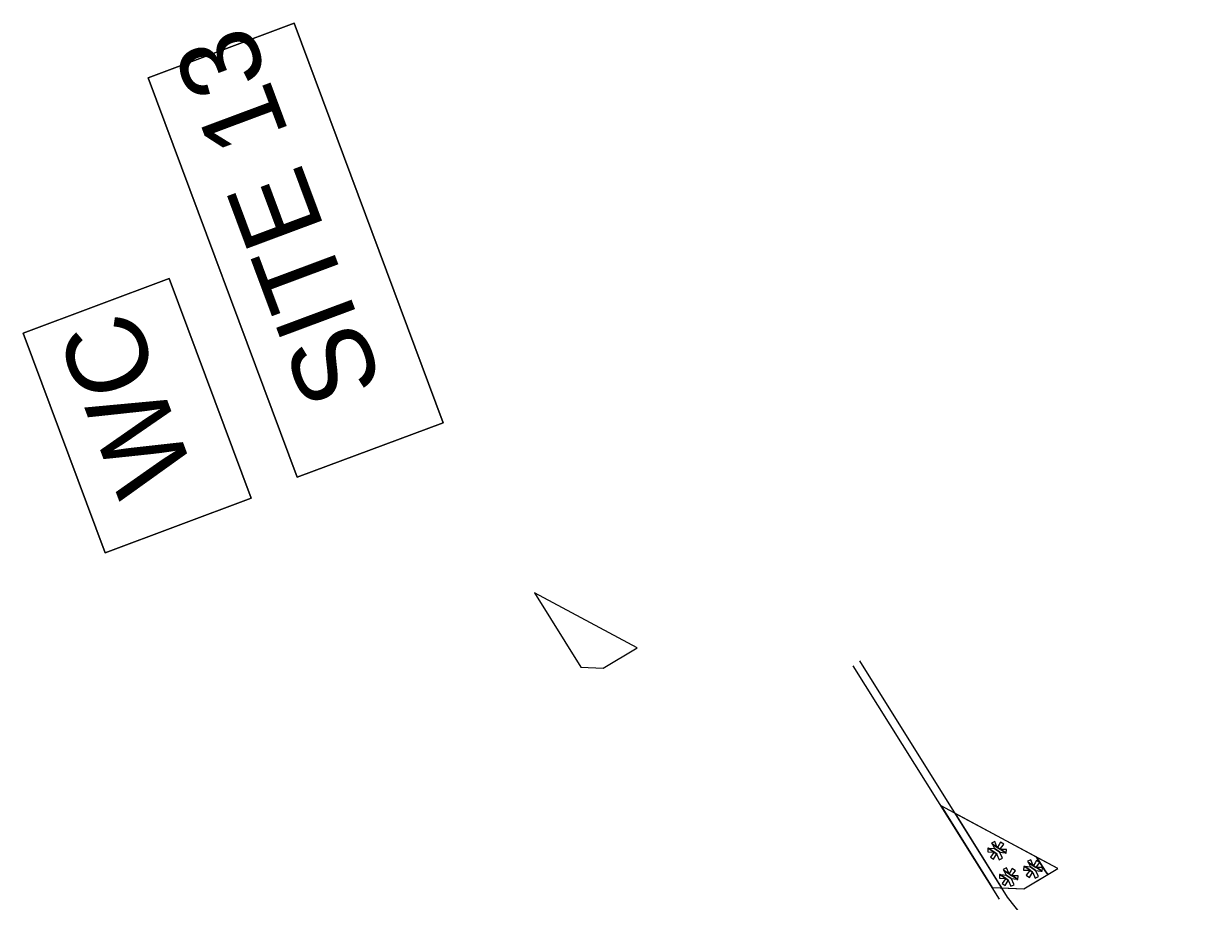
# Model space of a CAD drawing. Extents: x 474218 to 481634, y 484357 to 504997.
# Drawn here: x 478593.7 to 478809.9, y 494189.6 to 494353.5 of the extents above; entities that cross this region are included whole.
import ezdxf

# ---------------------------------------------------------------- set-up
doc = ezdxf.new("R2010")
doc.units = 0
for name, color, linetype in [('Old_Level_29', 7, 'Continuous'), ('Old_Level_30', 7, 'Continuous'), ('Prop Boundary Clearing Mechanized Hatching CELL', 7, 'Continuous'), ('Prop Earthen Structure Fill In Wetlands Hatching CELL', 7, 'Continuous'), ('Prop Grid Mask', 7, 'Continuous'), ('Scratch_Level_4', 7, 'Continuous')]:
    doc.layers.add(name, color=color, linetype=linetype)

msp = doc.modelspace()

# ---------------------------------------------------------------- linework, layer by layer
at = {"layer": 'Old_Level_29'}
msp.add_lwpolyline([(478644.82, 494268.8), (478616.99, 494343.34), (478644.25, 494353.52), (478672.07, 494278.98)], close=True, dxfattribs=at)
at = {"layer": 'Old_Level_30'}
msp.add_lwpolyline([(478608.97, 494254.73), (478593.68, 494295.7), (478620.92, 494305.87), (478636.22, 494264.9)], close=True, dxfattribs=at)
at = {"layer": 'Prop Boundary Clearing Mechanized Hatching CELL'}
msp.add_lwpolyline([(478774.49, 494192.29), (478780.36, 494192.02), (478784.89, 494194.73), (478784.34, 494195.41), (478782.75, 494197.94), (478764.94, 494207.5), (478774.49, 494192.29)], dxfattribs=at)
for points in [[(478775.38, 494199.88), (478775, 494200.86), (478774.38, 494200.58), (478774.47, 494200.41), (478775.44, 494199.73)], [(478776.91, 494198.73), (478777.08, 494198.7), (478776.07, 494199.4), (478775.93, 494199.41), (478775.45, 494199.74), (478775.44, 494199.73), (478774.47, 494200.41), (478774.92, 494199.53), (478775.88, 494198.86), (478776.88, 494198.73)], [(478776.33, 494199.94), (478776.64, 494200.34), (478776.06, 494200.74), (478775.8, 494200.31), (478775.8, 494200.3), (478775.49, 494199.81), (478775.45, 494199.74), (478775.93, 494199.41), (478775.97, 494199.47), (478776.33, 494199.93)], [(478774.83, 494198.89), (478774.86, 494198.89), (478773.84, 494199.59), (478773.8, 494199.6), (478773.69, 494199.61), (478773.64, 494198.92), (478774.73, 494198.89)], [(478775.9, 494198.81), (478775.88, 494198.86), (478774.92, 494199.53), (478774.95, 494199.47), (478773.84, 494199.59), (478774.86, 494198.89), (478774.85, 494198.87), (478775.32, 494198.55), (478775.36, 494198.45), (478775.79, 494197.44), (478775.79, 494197.44), (478776.41, 494197.73), (478776.36, 494197.82), (478776.35, 494197.85)], [(478775.29, 494198.5), (478775.32, 494198.55), (478774.85, 494198.87), (478774.82, 494198.83), (478774.14, 494197.96), (478774.71, 494197.57)], [(478777.13, 494199.37), (478777.13, 494199.38), (478777.12, 494199.38), (478776.07, 494199.4), (478777.08, 494198.7)], [(478777.56, 494194.96), (478777.17, 494195.94), (478776.55, 494195.66), (478776.64, 494195.48), (478777.62, 494194.81)], [(478778.51, 494195.01), (478778.81, 494195.42), (478778.24, 494195.81), (478777.98, 494195.38), (478777.97, 494195.38), (478777.67, 494194.88), (478777.63, 494194.82), (478778.1, 494194.49), (478778.15, 494194.55), (478778.5, 494195.01)], [(478781.54, 494195.5), (478781.57, 494195.49), (478780.55, 494196.2), (478780.52, 494196.21), (478780.4, 494196.22), (478780.35, 494195.53), (478781.44, 494195.5)], [(478782.61, 494195.42), (478782.59, 494195.47), (478781.63, 494196.14), (478781.66, 494196.08), (478780.55, 494196.2), (478781.57, 494195.49), (478781.56, 494195.48), (478782.03, 494195.16), (478782.07, 494195.06), (478782.5, 494194.05), (478782.5, 494194.05), (478783.12, 494194.34), (478783.07, 494194.43), (478783.06, 494194.46)], [(478782.09, 494196.49), (478781.71, 494197.47), (478781.09, 494197.19), (478781.18, 494197.02), (478782.15, 494196.34)], [(478783.62, 494195.33), (478783.79, 494195.31), (478782.78, 494196.01), (478782.64, 494196.02), (478782.16, 494196.35), (478782.15, 494196.34), (478781.18, 494197.02), (478781.63, 494196.14), (478782.59, 494195.47), (478783.59, 494195.34)], [(478783.04, 494196.55), (478783.35, 494196.95), (478782.78, 494197.34), (478782.51, 494196.91), (478782.51, 494196.91), (478782.2, 494196.41), (478782.16, 494196.35), (478782.64, 494196.02), (478782.69, 494196.08), (478783.04, 494196.54)], [(478783.84, 494195.98), (478783.84, 494195.99), (478783.84, 494195.99), (478782.78, 494196.01), (478783.79, 494195.31)], [(478777.01, 494193.96), (478777.03, 494193.96), (478776.01, 494194.67), (478775.98, 494194.68), (478775.87, 494194.69), (478775.82, 494194), (478776.91, 494193.97)], [(478778.08, 494193.89), (478778.05, 494193.94), (478777.1, 494194.6), (478777.13, 494194.55), (478776.01, 494194.67), (478777.03, 494193.96), (478777.03, 494193.95), (478777.49, 494193.63), (478777.54, 494193.53), (478777.97, 494192.52), (478777.97, 494192.52), (478778.58, 494192.81), (478778.54, 494192.9), (478778.52, 494192.93)], [(478777.47, 494193.58), (478777.49, 494193.63), (478777.03, 494193.95), (478776.99, 494193.91), (478776.32, 494193.04), (478776.88, 494192.65)], [(478779.08, 494193.8), (478779.26, 494193.78), (478778.25, 494194.48), (478778.1, 494194.49), (478777.63, 494194.82), (478777.62, 494194.81), (478776.64, 494195.48), (478777.1, 494194.6), (478778.05, 494193.94), (478779.06, 494193.81)], [(478779.31, 494194.45), (478779.31, 494194.46), (478779.3, 494194.46), (478778.25, 494194.48), (478779.26, 494193.78)], [(478782, 494195.11), (478782.03, 494195.16), (478781.56, 494195.48), (478781.53, 494195.44), (478780.85, 494194.57), (478781.42, 494194.18)]]:
    msp.add_lwpolyline(points, close=True, dxfattribs=at)
at = {"layer": 'Prop Earthen Structure Fill In Wetlands Hatching CELL'}
for p, q in [((478786.71, 494195.81), (478782.75, 494197.94)), ((478782.75, 494197.94), (478784.34, 494195.41)), ((478784.89, 494194.73), (478786.71, 494195.81)), ((478784.34, 494195.41), (478784.89, 494194.73))]:
    msp.add_line(p, q, dxfattribs=at)
at = {"layer": 'Prop Grid Mask'}
for points in [[(478672.07, 494278.98), (478644.25, 494353.52), (478616.99, 494343.34), (478644.82, 494268.8)], [(478636.22, 494264.9), (478620.92, 494305.87), (478593.68, 494295.7), (478608.97, 494254.73)]]:
    msp.add_lwpolyline(points, close=True, dxfattribs=at)
at = {"layer": 'Scratch_Level_4'}
for p, q in [((478775.87, 494190.1), (478748.54, 494233.62)), ((478777.31, 494190.49), (478749.79, 494234.55)), ((478809.87, 494149.8), (478777.31, 494190.49))]:
    msp.add_line(p, q, dxfattribs=at)
for points in [[(478697.75, 494233.38), (478701.87, 494233.19), (478708.23, 494236.98), (478689.08, 494247.26)], [(478776.23, 494192.21), (478780.36, 494192.02), (478786.71, 494195.81), (478767.57, 494206.09)]]:
    msp.add_lwpolyline(points, close=True, dxfattribs=at)

# ---------------------------------------------------------------- texts
at = {"layer": 'Old_Level_29'}
msp.add_text('SITE 13', height=15, rotation=110.4693, dxfattribs=at).set_placement((478660.93, 494285.92))
at = {"layer": 'Old_Level_30'}
msp.add_text('WC', height=15, rotation=110.4693, dxfattribs=at).set_placement((478625.72, 494269.39))

doc.saveas('drawing.dxf')
